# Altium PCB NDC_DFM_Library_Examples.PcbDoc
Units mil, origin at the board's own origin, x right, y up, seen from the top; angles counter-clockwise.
Board outline 8415 x 4965 mil, 4 copper layers (Top Layer, Mid-Layer 1, Mid-Layer 2, Bottom Layer); 33 components, 0 nets, 219 pads, 31 vias.
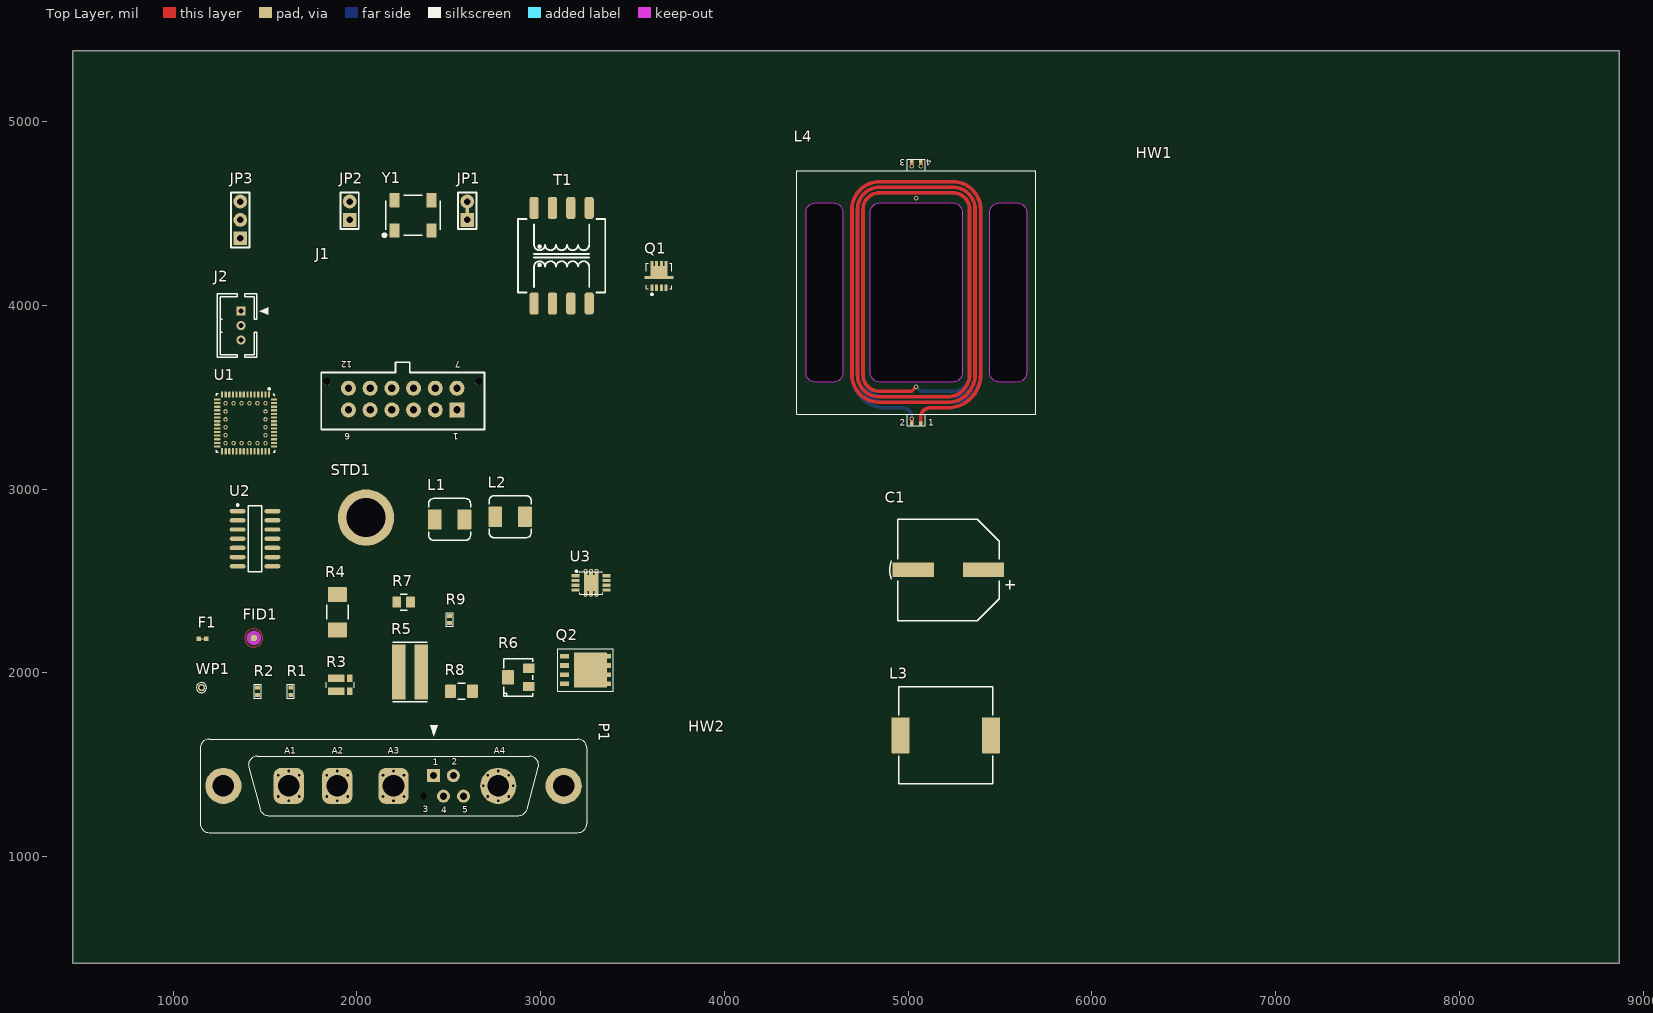
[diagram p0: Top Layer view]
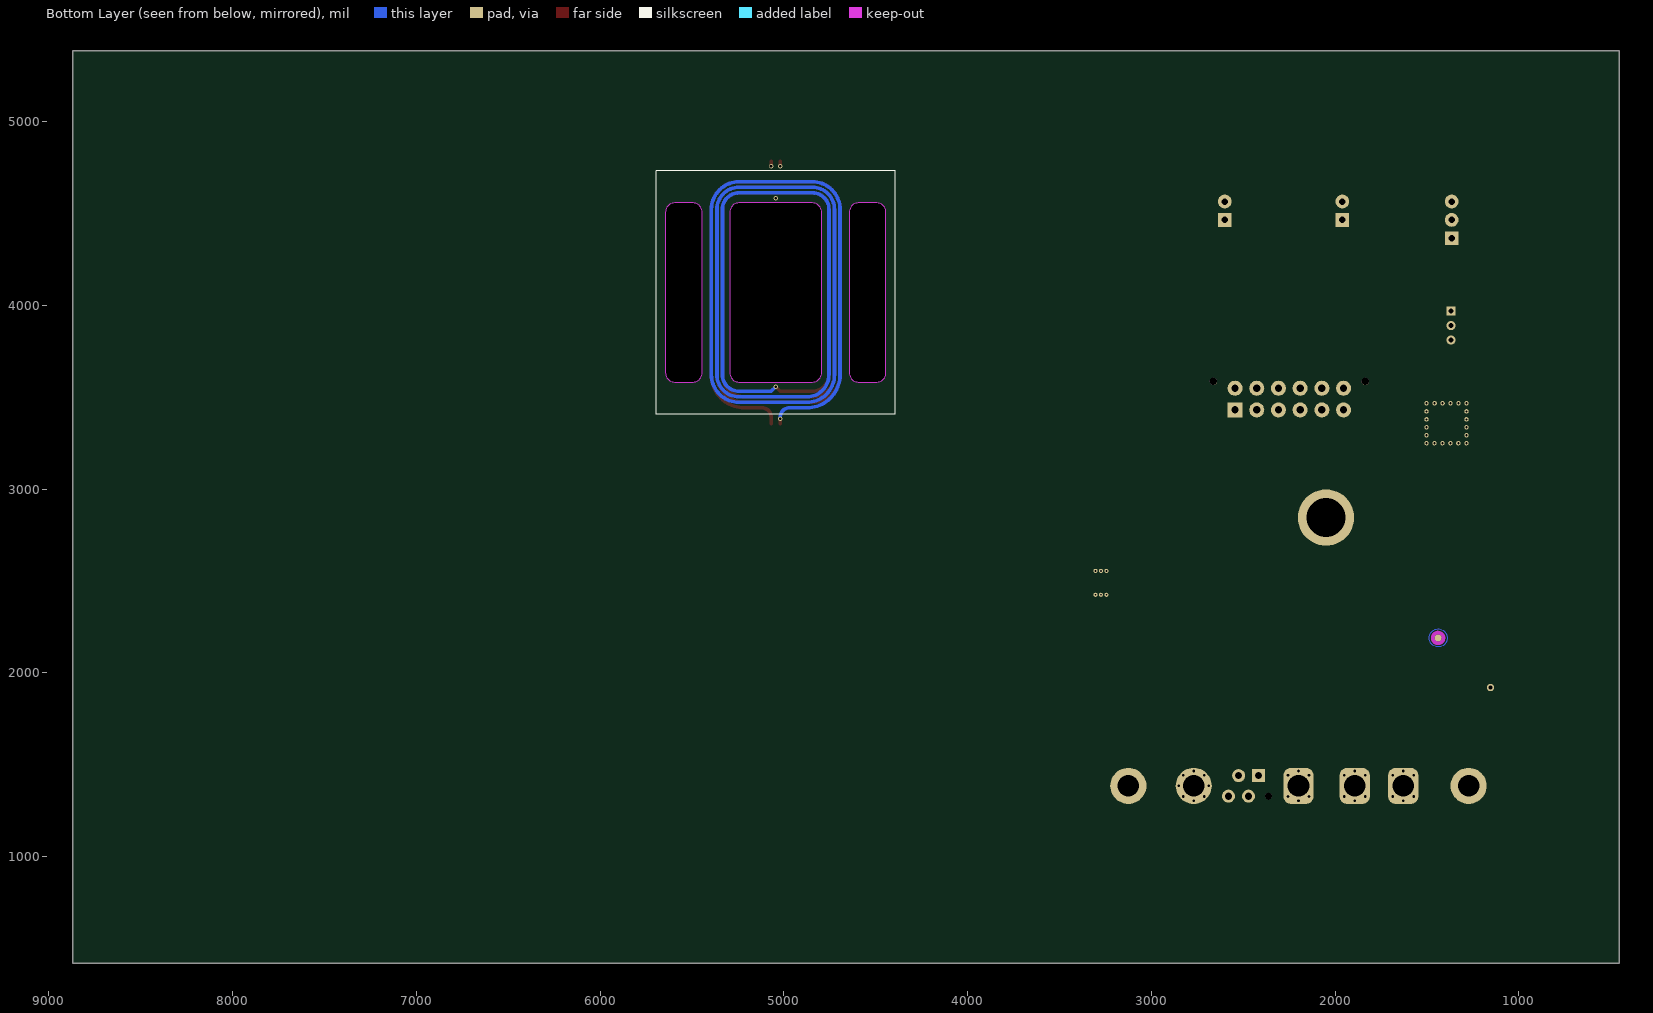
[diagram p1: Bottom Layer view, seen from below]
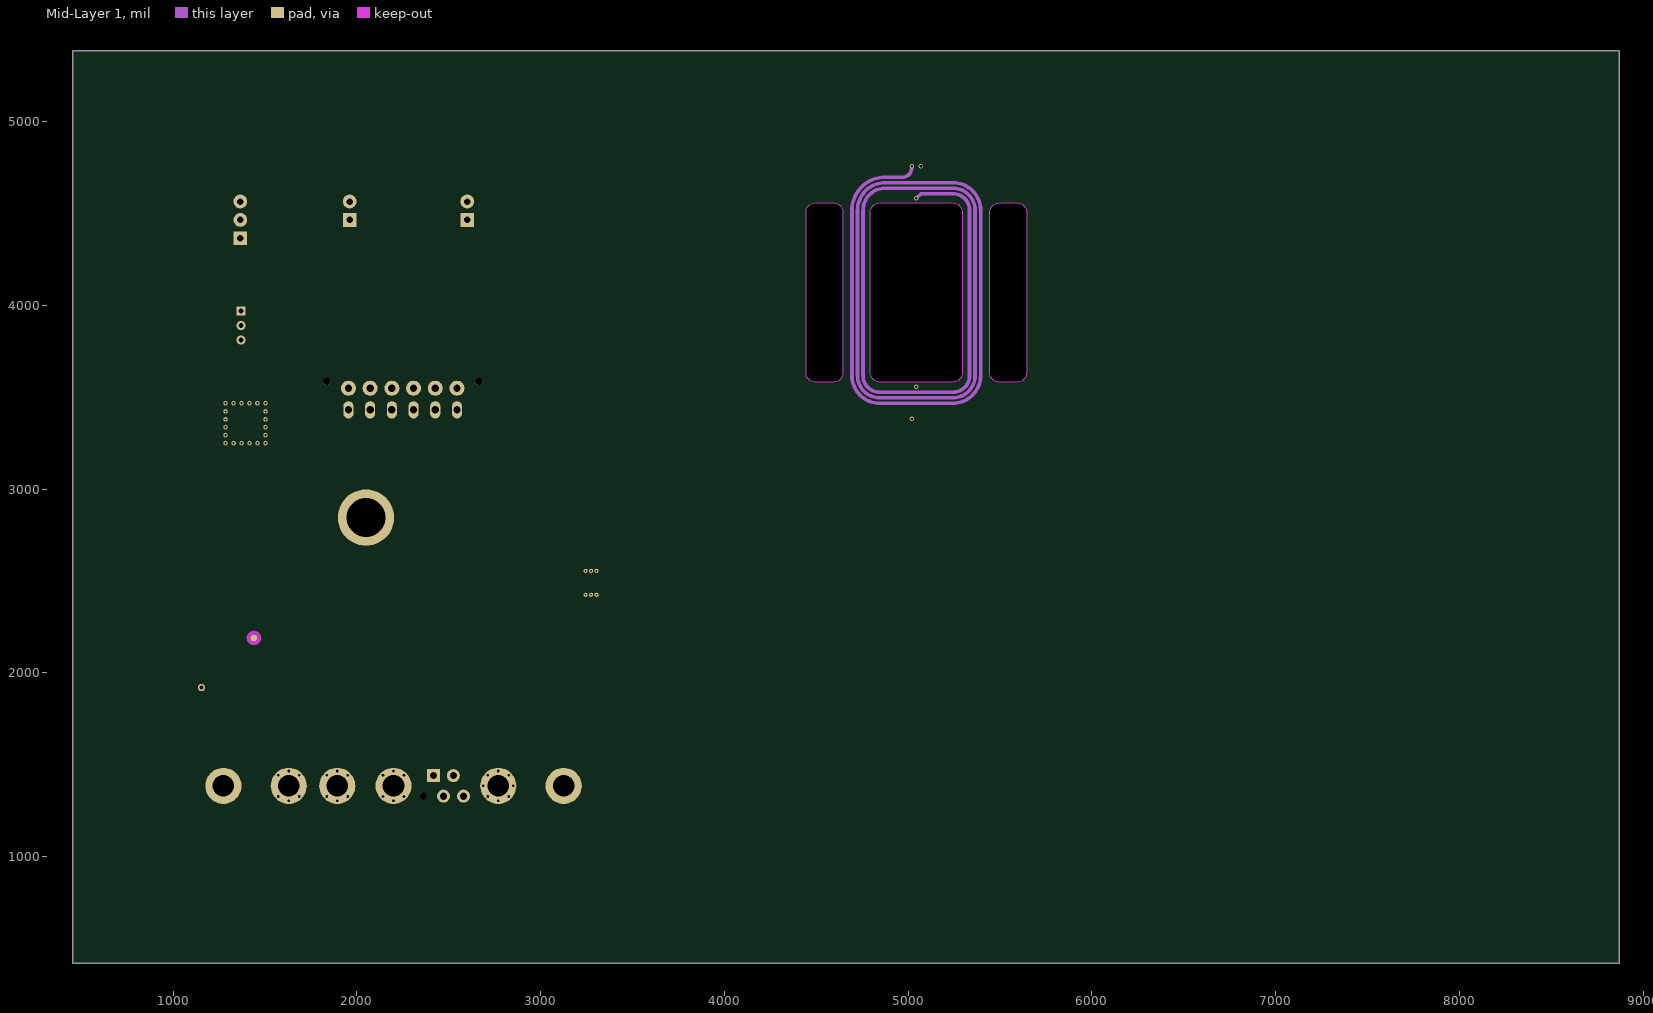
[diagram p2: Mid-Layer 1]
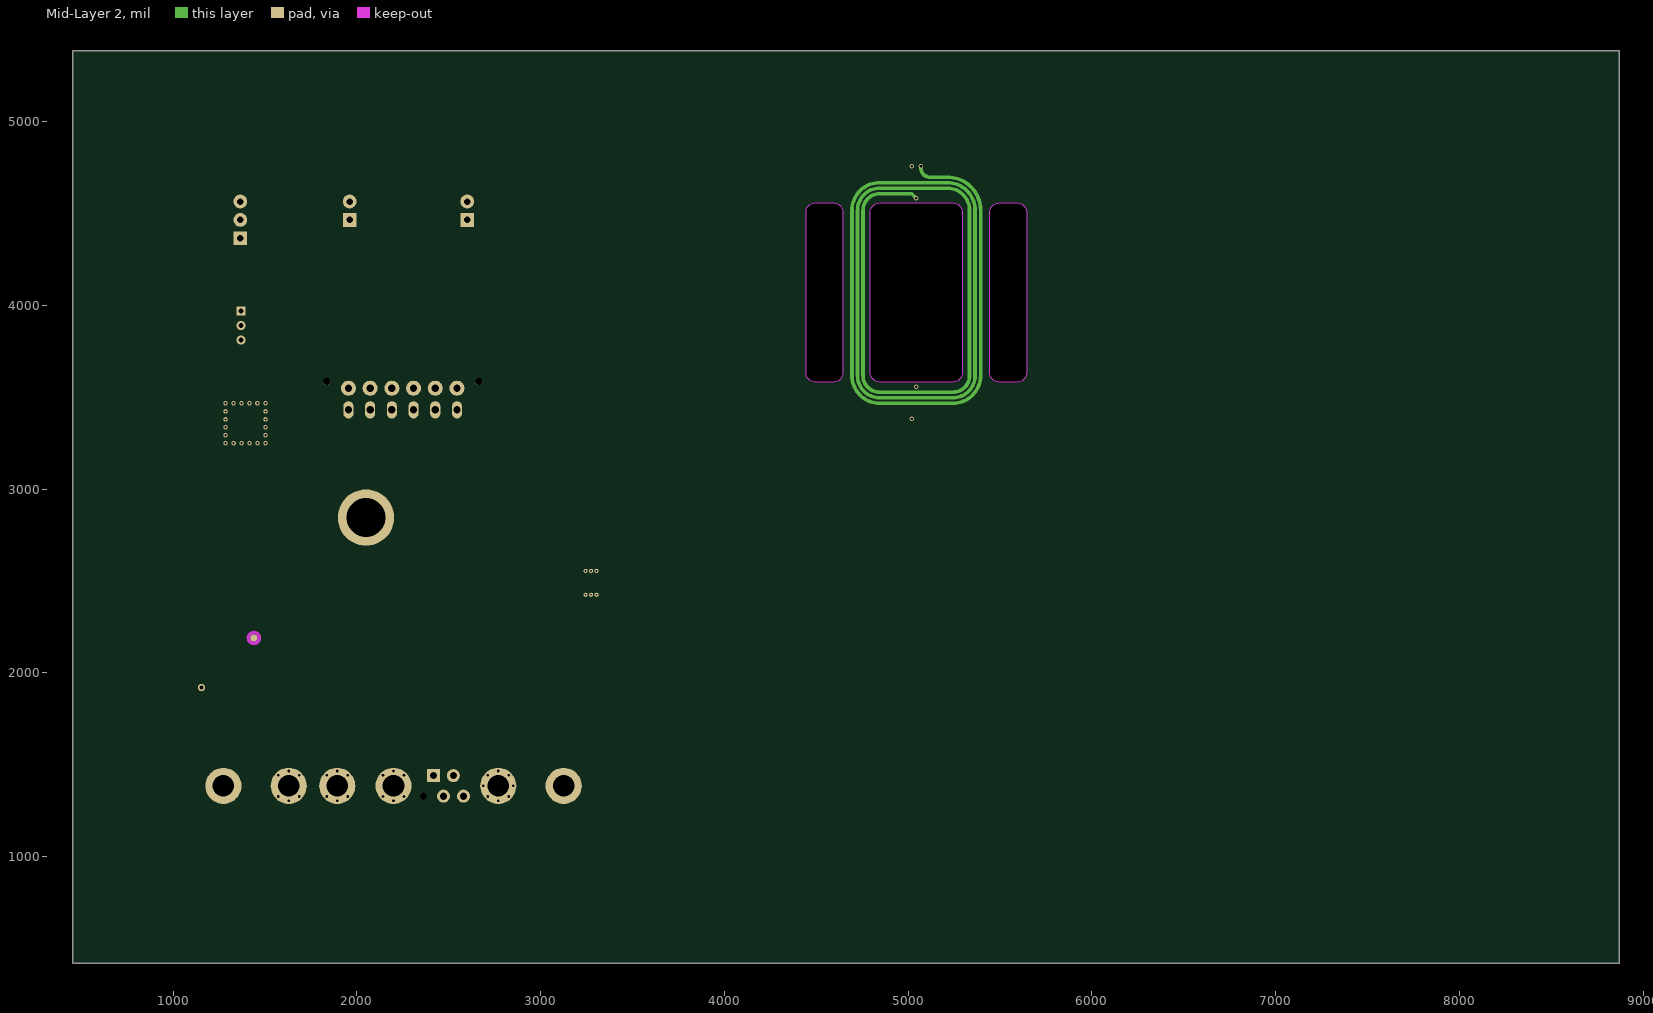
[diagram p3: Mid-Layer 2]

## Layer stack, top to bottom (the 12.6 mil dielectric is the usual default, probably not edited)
Top Solder: solder mask 0.4, Solder Resist, Dk 3.5
Top Layer: signal copper 1.4
Dielectric 1: dielectric 12.6, FR-4, Dk 4.8
Mid-Layer 1: signal copper 1.4
Dielectric2: dielectric 12.6, FR-4, Dk 4.8
Mid-Layer 2: signal copper 1.4
Dielectric3: dielectric 12.6, FR-4, Dk 4.8
Bottom Layer: signal copper 1.4
Bottom Solder: solder mask 0.4, Solder Resist, Dk 3.5

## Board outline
455,420 455,5385 8870,5385 8870,420

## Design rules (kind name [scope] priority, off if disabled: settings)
Clearance [All] p1: gap=10
Height [All] p1: minheight=0 maxheight=4000 prefheight=500
HoleSize [All] p1: absolutevalues=TRUE maxlimit=1000 minlimit=1 maxpercent=80.000 minpercent=20.000
PolygonConnect [All] p1: connectstyle=Relief reliefconductorwidth=10 reliefentries=4 polygonreliefangle="90 Angle" airgapwidth=10
RoutingVias [All] p1: holewidth=28 width=50 viastyle="Through Hole" minholewidth=7 minwidth=10 maxholewidth=1000 maxwidth=1000
SolderMaskExpansion [All] p1: expansion=4
Width [All] p1: maxlimit=30 minlimit=10 preferedwidth=10
28 further rules are at their usual default settings.

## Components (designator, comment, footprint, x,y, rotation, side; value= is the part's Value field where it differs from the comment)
C1 "CAP,ALUM,227,63V,20%,SMD" PANASONIC_CAP_SM_H13 5220,2560 r0 top
F1 "20A" PCB_FUSE-20A 1160,2185 r0 top net-tie
FID1 "FID" PCB_FID-TARGET-SM 1440,2190 r90 top
HW1 "HANDLE 3.00\"" KEYSTONE_HANDLE-7173 7230,4570 r0 top
HW2 "BRACKET,RA,6-32,THRD,0.165\"D,KEYSTONE,617" KEYSTONE_BRACKET-617 4100,1395 r0 top
J1 "HEADER,12P,MICROFIT,3MM DUAL V" MOLEX_43045-1212 2250,3490 r0 top
J2 "HEADER,3P,PH TOP,2MM" JST_B3B-PH-K-S 1370,3890 r90 top
JP1 "Breakaway Header, 0.1\"" TE_HDR1X2-CUT-TRACE 2601.24,4515.08 r90 top
JP2 "Breakaway Header, 0.1\"" TE_HDR1X2 1961.24,4465.08 r90 top
JP3 "Breakaway Header, 0.1\"" TE_HDR1X3 1366.24,4365.08 r90 top
L1 "IND,2.2uH,2020,5.5A,20%" VISHAY_IND-IHLP2020CZ-11 2505,2835 r0 top
L2 "IND,4.7uH,202,5.2A,20%" VISHAY_IND-IHLP2020CZ-11 2835,2850 r0 top
L3 "IND,250nH,SM,50A,81A ISAT" VISHAY-IND-WE-HCM 5205,1660 r0 top
L4 "IND,Etched" GENERIC_PLANAR-1:1 5045,4070 r90 top net-tie
P1 "JACK-M,9P,DSUB,MXD SIG" FCT_DB-9W4-M-S-PCB-MOD 2200,1385 r0 top
Q1 "TRAN,P-CH,PP1212-8,-60V,-8A" VISHAY_QFN65P330X330X112-10N 3645,4160 r90 top
Q2 "TRAN,N-CH,TDFN,60V,100A" INFINEON_TDSON-8 3245,2015 r0 top
R1 "RES,243K,0402,1%,1/16W" STACKPOLE_RESC1005X04N(0402) 1640,1900 r90 top
R2 "RES,1.4K,0402,1%,1/10W" STACKPOLE_RESC1005X04N(0402) 1460,1900 r90 top
R3 "RES-SENSOR,R004,0612,1%,1W" VISHAY_RES1632(0612)-RSNS 1910,1935 r0 top
R4 "RES,750K,MELF0204,1%,1W" VISHAY_MELF-MMB-0207 1895,2330 r90 top
R5 "RES,4.7K,1225WIDE,1%,2W" VISHAY_RES3263(1225) 2290,2005 r90 top
R6 "RES-POT,10K,SM,10%,1/4W" RPOT_3224W_44W 2880,1975 r0 top
R7 "RES,35.7K,MELF010,0.1%,1/5W" VISHAY_MELF-MMU-0102 2255,2385 r0 top
R8 "RES,100K,MELF0204,0.1%,1/4W" VISHAY_MELF-MMA-0204 2570,1900 r0 top
R9 "RES,0R00,0402,1/10W" STACKPOLE_RESC1005X04N(0402) 2505,2290 r90 top
STD1 "STANDOFF,PEM,3.6X4,CS,SMT" PENN_PEM-SMTSO-3.6-4DT 2050,2845 r0 top
T1 "XFRMR,1:1,SMD" PPT_PT4812 3115,4270 r0 top
U1 "IC_CYPRESS_USB-INTERFACE_CY7C68001-56LFC" CYPRESS_QFN50P800X800-HS-57 1395,3360 r0 top
U2 "IC_QUAD-AND-GATE_SN74HCT08DR_TI" TI_SOIC_14 1446.24,2730.08 r0 top
U3 "DISCRETE_OP-AMP_THS4631DGN_TI" TI_DGN8-EP 3275,2490 r0 top
WP1 "PAD,WIRE,28AWG,TH" GENERIC_WP28 1155,1920 r0 top
Y1 "ECS-3953M-1000-AU-TR" ECS_3953M-1000-AU-TR 2306.24,4490.08 r0 top

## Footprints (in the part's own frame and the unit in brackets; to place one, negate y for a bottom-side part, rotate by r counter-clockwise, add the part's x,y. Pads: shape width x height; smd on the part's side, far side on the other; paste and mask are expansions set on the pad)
CYPRESS_QFN50P800X800-HS-57 [mm] "Quad Flat No Lead; 56 Terminals; Body 8 x 8 mm; Pitch 0.5 mm, Punch Version"
  rrect50% 0.305x0.86 smd mask+0.051: 1(3.25,3.92) 14(-3.25,3.92) 29(-3.25,-3.92) 42(3.25,-3.92)
  rrect50% 0.305x0.86 smd mask+0.038: 2(2.75,3.92) 3(2.25,3.92) 4(1.75,3.92) 5(1.25,3.92) 6(0.75,3.92) 7(0.25,3.92) 8(-0.25,3.92) 9(-0.75,3.92) 10(-1.25,3.92) 11(-1.75,3.92) 12(-2.25,3.92) 13(-2.75,3.92) 30(-2.75,-3.92) 31(-2.25,-3.92) 32(-1.75,-3.92) 33(-1.25,-3.92) 34(-0.75,-3.92) 35(-0.25,-3.92) 36(0.25,-3.92) 37(0.75,-3.92) 38(1.25,-3.92) 39(1.75,-3.92) 40(2.25,-3.92) 41(2.75,-3.92)
  rrect50% 0.86x0.305 smd mask+0.051: 15(-3.92,3.25) 28(-3.92,-3.25) 43(3.92,-3.25) 56(3.92,3.25)
  rrect50% 0.86x0.305 smd mask+0.038: 16(-3.92,2.75) 17(-3.92,2.25) 18(-3.92,1.75) 19(-3.92,1.25) 20(-3.92,0.75) 21(-3.92,0.25) 22(-3.92,-0.25) 23(-3.92,-0.75) 24(-3.92,-1.25) 25(-3.92,-1.75) 26(-3.92,-2.25) 27(-3.92,-2.75) 44(3.92,-2.75) 45(3.92,-2.25) 46(3.92,-1.75) 47(3.92,-1.25) 48(3.92,-0.75) 49(3.92,-0.25) 50(3.92,0.25) 51(3.92,0.75) 52(3.92,1.25) 53(3.92,1.75) 54(3.92,2.25) 55(3.92,2.75)
  round 0.6 hole 0.3: 56(-2.775,-2.8) 56(-2.775,-1.7) 56(-2.775,-0.6) 56(-2.775,0.5) 56(-2.775,1.6) 56(-2.775,2.725) 56(-1.675,2.725) 56(-1.65,-2.8) 56(-0.575,2.725) 56(-0.55,-2.8) 56(0.525,2.725) 56(0.55,-2.8) 56(1.625,2.725) 56(1.65,-2.8) 56(2.75,-2.8) 56(2.75,-1.7) 56(2.75,-0.6) 56(2.75,0.5) 56(2.75,1.6) 56(2.75,2.725)
  silkscreen extent -4.05,-4.05 4.05,4.83, body extent -4.27,-4.32 4.31,4.2, height 0.55
ECS_3953M-1000-AU-TR [mm] "SMD CLOCK OSCILLATOR"
  rrect10% 1.4x2 smd: 1(-2.54,-2.1) 2(2.54,-2.1) 3(2.54,2.1) 4(-2.54,2.1)
  silkscreen extent -4.15,-2.95 3.75,2.75, body extent -3.5,-2.5 3.5,2.5, height 1.71
FCT_DB-9W4-M-S-PCB-MOD [mm] "FCT FM9W4P1-2464, Conn, DB, Mixed, 9 Pins, 4 Wide, Male, Straight, PCB Mt"
  rect 1.803x1.803 hole 1: 1(5.54,1.42)
  round 1.803 hole 1: 2(8.28,1.42) 4(6.91,-1.42) 5(9.68,-1.42)
  round 0.889 hole 1 unplated: 3(4.14,-1.42)
  rrect50% 4.2x5 / inner round 5 / far side rrect50% 4.2x5 hole 3: A1(-14.48,0) A2(-7.77,0) A3(0,0)
  round 5 hole 3: A4(14.48,0) C(-23.52,0) C(23.52,0)
  silkscreen extent -26.7,-6.45 26.7,8.38, body extent -26.47,-6.27 26.53,6.23, height 13.8
GENERIC_PLANAR-1:1 [mil]
  rrect10% 20x20 smd paste-50 mask-50: 1(-712.5,-25) 2(-712.5,25) 3(712.5,25) 4(712.5,-25)
  Top Layer lines w20: -712.5,25 -687.5,25 ; 687.5,25 712.5,25 ; -512.5,0 -537.5,25 -537.5,200 cw(c-447.5,200) -447.5,290 452.5,290 cw(c452.5,200) 542.5,200 542.5,-200 cw(c452.5,-200) 452.5,-290 -447.5,-290 cw(c-447.5,-170) -567.5,-170 -567.5,0 -567.5,200 cw(c-447.5,200) -447.5,320 452.5,320 cw(c452.5,200) 572.5,200 572.5,-200 cw(c452.5,-200) 452.5,-320 -447.5,-320 cw(c-447.5,-170) -597.5,-170 -597.5,0 -597.5,200 cw(c-447.5,200) -447.5,350 452.5,350 cw(c452.5,200) 602.5,200 602.5,-200 cw(c452.5,-200) 452.5,-350 -447.5,-350 cw(c-447.5,-170) -627.5,-170 -627.5,-75 ccw(c-677.5,-75) -677.5,-25 -712.5,-25 ; 687.5,-25 712.5,-25
  Mid-Layer 1 lines w20: 687.5,25 677.5,25 cw(c677.5,75) 627.5,75 627.5,170 ccw(c447.5,170) 447.5,350 -452.5,350 ccw(c-452.5,200) -602.5,200 -602.5,-200 ccw(c-452.5,-200) -452.5,-350 447.5,-350 ccw(c447.5,-200) 597.5,-200 597.5,0 597.5,170 ccw(c447.5,170) 447.5,320 -452.5,320 ccw(c-452.5,200) -572.5,200 -572.5,-200 ccw(c-452.5,-200) -452.5,-320 447.5,-320 ccw(c447.5,-200) 567.5,-200 567.5,0 567.5,170 ccw(c447.5,170) 447.5,290 -452.5,290 ccw(c-452.5,200) -542.5,200 -542.5,-200 ccw(c-452.5,-200) -452.5,-290 447.5,-290 ccw(c447.5,-200) 537.5,-200 537.5,-25 512.5,0
  Mid-Layer 2 lines w20: 512.5,0 537.5,25 537.5,200 ccw(c447.5,200) 447.5,290 -452.5,290 ccw(c-452.5,200) -542.5,200 -542.5,-200 ccw(c-452.5,-200) -452.5,-290 447.5,-290 ccw(c447.5,-170) 567.5,-170 567.5,0 567.5,200 ccw(c447.5,200) 447.5,320 -452.5,320 ccw(c-452.5,200) -572.5,200 -572.5,-200 ccw(c-452.5,-200) -452.5,-320 447.5,-320 ccw(c447.5,-170) 597.5,-170 597.5,0 597.5,200 ccw(c447.5,200) 447.5,350 -452.5,350 ccw(c-452.5,200) -602.5,200 -602.5,-200 ccw(c-452.5,-200) -452.5,-350 447.5,-350 ccw(c447.5,-170) 627.5,-170 627.5,-75 cw(c677.5,-75) 677.5,-25 687.5,-25
  Bottom Layer lines w20: -687.5,25 -677.5,25 ccw(c-677.5,75) -627.5,75 -627.5,170 cw(c-447.5,170) -447.5,350 452.5,350 cw(c452.5,200) 602.5,200 602.5,-200 cw(c452.5,-200) 452.5,-350 -447.5,-350 cw(c-447.5,-200) -597.5,-200 -597.5,0 -597.5,170 cw(c-447.5,170) -447.5,320 452.5,320 cw(c452.5,200) 572.5,200 572.5,-200 cw(c452.5,-200) 452.5,-320 -447.5,-320 cw(c-447.5,-200) -567.5,-200 -567.5,0 -567.5,170 cw(c-447.5,170) -447.5,290 452.5,290 cw(c452.5,200) 542.5,200 542.5,-200 cw(c452.5,-200) 452.5,-290 -447.5,-290 cw(c-447.5,-200) -537.5,-200 -537.5,-25 -512.5,0
  Keep-Out Layer board cut-out: -487.5,-550 -487.5,-450 -483.69,-430.87 -472.85,-414.64 -456.63,-403.81 -437.5,-400 -437.5,-400 437.5,-400 456.63,-403.81 472.86,-414.64 483.69,-430.87 487.5,-450 487.5,-450 487.5,-550 483.69,-569.13 472.86,-585.35 456.63,-596.19 437.5,-600 437.5,-600 -437.5,-600 -456.63,-596.19 -472.85,-585.35 -483.69,-569.13 -487.5,-550
  Keep-Out Layer board cut-out: -487.5,450 -487.5,550 -483.69,569.13 -472.85,585.36 -456.63,596.19 -437.5,600 -437.5,600 437.5,600 456.63,596.19 472.86,585.36 483.69,569.13 487.5,550 487.5,550 487.5,450 483.69,430.87 472.86,414.65 456.63,403.81 437.5,400 437.5,400 -437.5,400 -456.63,403.81 -472.85,414.65 -483.69,430.87 -487.5,450
  Keep-Out Layer board cut-out: -487.5,-200 -487.5,200 -483.69,219.13 -472.85,235.36 -456.63,246.19 -437.5,250 -437.5,250 437.5,250 456.63,246.19 472.86,235.36 483.69,219.13 487.5,200 487.5,200 487.5,-200 483.69,-219.13 472.86,-235.35 456.63,-246.19 437.5,-250 437.5,-250 -437.5,-250 -456.63,-246.19 -472.85,-235.35 -483.69,-219.13 -487.5,-200
  silkscreen extent -725,-650 725,650, body extent -462,-575 463,575, height 70
GENERIC_WP28 [mil] "PAD,WIRE,28AWG,TH"
  round 40 hole 22: WP28(0,0)
  silkscreen extent -27,-27 28,27, body extent -12,-12 12,12, height 258
INFINEON_TDSON-8 [mm] "INFINEON  SuperS08 125W"
  rect 4.6x4.8 smd: D(0.7,0)
  rect 1.2x0.65 smd: D(2.9,-1.905) D(2.9,-0.635) D(2.9,0.635) D(2.9,1.905) G(-2.9,-1.905) S(-2.9,-0.635) S(-2.9,0.635) S(-2.9,1.905)
  silkscreen extent -3.81,-2.92 3.81,2.92, body extent -3.12,-2.63 3.12,2.63, height 1.12
JST_B3B-PH-K-S [mm]
  rrect15% 1.25x1.25 hole 0.7: 1(2,0)
  round 1.25 hole 0.7: 2(0,0) 3(-2,0)
  silkscreen extent -4.4,-3.75 4.4,3.3, body extent -3.95,-1.7 3.95,2.8, height 6
KEYSTONE_BRACKET-617 [mil] "BRACKET,RIGHT-ANGL,THRD,6-32 (STEEL)"
  body extent -299,-250 201,250, height 578
KEYSTONE_HANDLE-7173 [mil] "HANDLE,ALUM,BLK,3.00\",8-32"
  body extent -125,-3125 125,125, height 1828
MOLEX_43045-1212 [mm] "Header, 12 Position, Pitch 3.0mm, Body 21.65 mm L X 7.37mm W, Height 9.91mm"
  rect 2.083x2.083 / inner oval 1.4x2.4 / far side rect 2.083x2.083 hole 1.02 mask+0.051: 1(7.5,-1.5)
  round 2.083 / inner oval 1.4x2.4 / far side round 2.083 hole 1.02 mask+0.051: 2(4.5,-1.5) 3(1.5,-1.5) 4(-1.5,-1.5) 5(-4.5,-1.5) 6(-7.5,-1.5)
  round 2.083 hole 1.02 mask+0.051: 7(7.5,1.5) 8(4.5,1.5) 9(1.5,1.5) 10(-1.5,1.5) 11(-4.5,1.5) 12(-7.5,1.5)
  round 1.016 hole 1.02 unplated: MNT(-10.5,2.44) MNT(10.5,2.44)
  silkscreen extent -11.25,-4.22 11.3,5.1, body extent -11.07,-4.39 11.08,6.46, height 25
PANASONIC_CAP_SM_H13 [mm]
  rect 5.7x2 smd: 1(4.85,0) 2(-4.85,0)
  silkscreen extent -8.11,-7 9.15,7, body extent -6.9,-6.75 6.9,6.75, height 13.5
PCB_FID-TARGET-SM [mm]
  round 1 on Mech6 paste-0.55 mask+1: FID1(0,0)
  round 1 all layers, no hole paste-0.762 mask+0.9: FIDM(0,0)
  Top Layer circle w0.155: c0,0 r1.25
  Bottom Layer circle w0.155: c0,0 r1.25
  Keep-Out Layer circle w0.5: c0,0 r0.75
PCB_FUSE-20A [mm]
  rect 0.6x0.6 smd: 1(-0.527,-0.001) 2(0.523,-0.001)
  rrect10% 1x0.125 smd paste-2 mask-2: 1(0,0)
PENN_PEM-SMTSO-3.6-4DT [mm] "PEM Standoff SMTSO-3.6-4DT, Matte Tin, Surface Mount Solder, ReelFast"
  round 7.77 hole 5.41: MH(0,0)
  body extent -3.57,-3.57 3.57,3.57, height 4
PPT_PT4812 [mm] "Transformer for Digital Audio Data Transmission"
  rrect50% 1.27x3.05 smd: 1(3.81,6.605) 2(1.27,6.605) 3(-1.27,6.605) 4(-3.81,6.605) 5(-3.81,-6.605) 6(-1.27,-6.605) 7(1.27,-6.605) 8(3.81,-6.605)
  silkscreen extent -6.03,-5.08 6.03,5.08, body extent -5.97,-6.64 6.09,6.89, height 8.86
RPOT_3224W_44W [mm] "Potentiometer, SMT 4mm, Multiturn Cermet, Sealed"
  rrect10% 1.6x1.3 smd: 1(1.45,1.25) 3(1.45,-1.25)
  rrect10% 1.6x2 smd: 2(-1.45,0)
  silkscreen extent -2,-2.6 2,2.6, body extent -1.96,-2.41 1.97,2.41, height 5.28
STACKPOLE_RESC1005X04N(0402) [mm] "Chip Resistor, Body 1.0x0.5mm, Height 0.40mm, IPC Medium Density"
  rect 0.55x0.65 smd: 1(-0.5,0) 2(0.5,0)
  silkscreen extent -0.95,-0.5 0.95,0.5, body extent -0.52,-0.27 0.53,0.28, height 0.45
TE_HDR1X2 [mm] "Connector; Header; 2 Position"
  rect 1.905x1.905 hole 0.9: 1(0,0)
  round 1.905 hole 0.9: 2(2.54,0)
  silkscreen extent -1.27,-1.27 3.81,1.27, body extent -1.27,-1.27 3.81,1.27, height 8.25
TE_HDR1X2-CUT-TRACE [mm] "Connector; Header; 2 Position"
  rect 1.905x1.905 hole 0.9: 1(-1.27,0)
  rrect10% 2.54x0.508 smd paste-2.667 mask-2.667: 1(0,0)
  round 1.905 hole 0.9: 2(1.27,0)
  silkscreen extent -2.54,-1.27 2.54,1.27, body extent -2.54,-1.27 2.54,1.27, height 8.25
TE_HDR1X3 [mm] "Connector; Header; 3 Position"
  rect 1.905x1.905 hole 0.9: 1(0,0)
  round 1.905 hole 0.9: 2(2.54,0) 3(5.08,0)
  silkscreen extent -1.27,-1.27 6.35,1.27, body extent -1.27,-1.27 6.35,1.27, height 8.25
TI_DGN8-EP [mil] "TSOP, 8-Leads, Body 3.1x3.1mm (max), Pitch 0.65mm, IPC Medium Density"
  rect 45x17.72 smd mask+0: 1(-84,38.39) 2(-84,12.8) 3(-84,-12.8) 4(-84,-38.39) 5(84,-38.39) 6(84,-12.8) 7(84,12.8) 8(84,38.39)
  round 22 hole 10: 9(-29.53,-65) 9(-29.53,65) 9(0,-65) 9(0,65) 9(29.53,-65) 9(29.53,65)
  rect 20x30 smd: 9(-29.53,-48.23) 9(-29.53,47.24) 9(0,-49.21) 9(0,47.24) 9(29.53,-49.21) 9(29.53,46.26)
  rect 78.74x86.61 smd: 9(0,0)
  silkscreen extent -84,-61 61,68, body extent -96,-59 97,59, height 38
TI_SOIC_14 [mm] "SOIC, 14-Leads, Body 8.65x3.95mm, Pitch 1.27mm, IPC Medium Density"
  oval 2.2x0.6 smd: 1(-2.4,3.81) 2(-2.4,2.54) 3(-2.4,1.27) 4(-2.4,0) 5(-2.4,-1.27) 6(-2.4,-2.54) 7(-2.4,-3.81) 8(2.4,-3.81) 9(2.4,-2.54) 10(2.4,-1.27) 11(2.4,0) 12(2.4,1.27) 13(2.4,2.54) 14(2.4,3.81)
  silkscreen extent -2.52,-4.55 0.9,4.78, body extent -2.9,-4.26 2.9,4.26, height 1.75
VISHAY-IND-WE-HCM [mm] "WE-HCM SMD High-Current Flat Wire Inductor"
  rrect10% 2.5x5 smd: 1(-6.25,0) 2(6.25,0)
  silkscreen extent -6.5,-6.7 6.5,6.7, body extent -7,-6.5 7,6.5, height 9
VISHAY_IND-IHLP2020CZ-11 [mm] "Low Profile, High Current IHLP® Inductor"
  rrect10% 1.9x2.8 smd: 1(-2.05,0) 2(2.05,0)
  silkscreen extent -2.9,-2.9 2.9,2.9, body extent -2.75,-2.6 2.75,2.6, height 3
VISHAY_MELF-MMA-0204 [mm]
  rrect10% 1.5x1.8 smd: 1(-1.5,0) 2(1.5,0)
  silkscreen extent -0.5,-1.1 0.5,1.1, body extent -1.7,-0.7 1.7,0.7, height 1.4
VISHAY_MELF-MMB-0207 [mm]
  rrect10% 2.1x2.6 smd: 1(-2.45,0) 2(2.45,0)
  silkscreen extent -1,-1.5 1,1.5, body extent -2.65,-1.1 2.65,1.1, height 2.2
VISHAY_MELF-MMU-0102 [mm]
  rrect10% 1.2x1.5 smd: 1(-0.95,0) 2(0.95,0)
  silkscreen extent -0.5,-1.1 0.5,1.1, body extent -1,-0.55 1,0.55, height 1.1
VISHAY_QFN65P330X330X112-10N [mm] "QFN, 10-Leads, Body 3.4x3.4mm (max), Pitch 0.65mm, IPC Medium Density"
  rect 0.9x0.4 smd: 1(-1.625,0.975) 2(-1.625,0.325) 3(-1.625,-0.325) 4(-1.625,-0.975) 6(1.625,-0.975) 7(1.625,-0.325) 8(1.625,0.325) 9(1.625,0.975)
  rect 0.4x0.95 smd: 5(-0.203,1.524) 5(-0.203,-1.524)
  rect 1.8x2.4 smd: 5(0.5,0)
  silkscreen extent -2.67,-1.75 1.75,1.75, body extent -1.63,-1.7 1.64,1.7, height 1.13
VISHAY_RES1632(0612)-RSNS [mil] "4-Terminal, 1W, Current-sense Resistor"
  rrect10% 90x40 smd: 1(-22.5,35) 2(-22.5,-35)
  rrect10% 30x40 smd: 1(52.5,35) 2(52.5,-35)
  silkscreen extent -75,-15 75,15, body extent -60,-30 60,30, height 15
VISHAY_RES3263(1225) [mm] "Long Side Termination Thick Film Chip Resistor, 2W"
  rrect10% 7.6x1.9 smd: 1(0,1.55) 2(0,-1.55)
  silkscreen extent -4.1,-2.4 4.1,2.4, body extent -3.15,-1.55 3.15,1.55, height 0.63

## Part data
C1: library part DISCRETE_CAP_SM_227uF_63V_H13.5_PANASONIC
F1: library part PCB_FUSE-20A, "PCB FEATURE"
FID1: library part PCB_FID-TARGET-SM, "PCB FEATURE"
HW1: library part MECH_HANDLE_RACK_3IN_KEYSTONE, "HANDLE,ALUM,BLK,3.00\",8-32"
HW2: library part MECH_BRACKET_RA_KEYSTONE
J1: library part CONN_43045-1212_MOLEX
J2: library part CONN_B3B-PH-K-S_JST
JP1: library part CONN_JUMPER-2PIN-CUT-TRACE_TE, "Breakaway Header, 2.54mm (0.1\") Pitch"
JP2: library part CONN_JUMPER-2PIN_TE, "Breakaway Header, 2.54mm (0.1\") Pitch"
JP3: library part CONN_JUMPER-3PIN_TE, "Breakaway Header, 2.54mm (0.1\") Pitch"
L1: library part DISCRETE_IND-SM_2.2uH_5.5A_20%_VISHAY
L2: library part DISCRETE_IND-SM_4.7uH_5.2A_20%_VISHAY
L3: library part DISCRETE_IND-SM_250NH_50A_VISHAY
L4: library part PCB_IND-SM
P1: library part CONN_DB-9W4-M-S-PCB_FCT
Q1: library part DISCRETE_TRAN-SM_P-CH_SI7309DN_PP1212-8_VISHAY
Q2: library part DISCRETE_TRAN-SM_N-CH_60V_100A_TDSON-8_INFINEON
R1: library part DISCRETE_RES0402_243K_1%_1/16W_STACKPOLE
R2: library part DISCRETE_RES0402_1.4K_1%_1/10W_PANASONIC
R3: library part DISCRETE_RES0612_R004_1%_1W_VISHAY, "RES,R004,0612,1%,1W"
R4: library part DISCRETE_RES_MELF_0207_750K_1%_1W_VISHAY
R5: library part DISCRETE_RES1225_4.7K_1%_2W_1225WIDE_VISHAY
R6: library part DISCRETE_RES-SM-POT_10K_MULTI_1/4W_BiTECH
R7: library part DISCRETE_RES_MELF_010_35.7K_0.1%_1/5W_VISHAY
R8: library part DISCRETE_RES_MELF_0204_100K_0.1%_1/4W_VISHAY
R9: library part DISCRETE_RES0402_0R00_PANASONIC
STD1: library part MECH_STANDOFF_PEM_3.6X4_CS_SMT_PENN
T1: library part DISCRETE_XFRMR_PT4812_PPT
U1: "CY7C68001-56LFC, EZ-USB SX2 High-Speed USB Interface"
U2: "LogicGate_AND"
U3: "Operational Amplifier"
WP1: library part PCB_WIRE_PAD_28AWG
Y1: library part IC_ECS_OSC-100.000-MHZ-3.3V-SMD, "OSC 100.000 MHZ 3.3V SMD"

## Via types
v1: diameter 32, hole 15, Top Layer to Bottom Layer, 26 vias
v2: diameter 25, hole 15, Top Layer to Bottom Layer, tented both sides, 5 vias

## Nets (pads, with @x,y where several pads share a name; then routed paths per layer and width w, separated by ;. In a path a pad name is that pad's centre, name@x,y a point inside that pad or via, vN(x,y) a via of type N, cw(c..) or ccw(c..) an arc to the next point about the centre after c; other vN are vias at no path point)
pads on no net: C1.1 C1.2 F1.1 F1.2 FID1.FID1 FID1.FIDM J1.1 J1.2 J1.3 J1.4 J1.5 J1.6 J1.7 J1.8 J1.9 J1.10 J1.11 J1.12 J1.MNT J2.1 J2.2 J2.3 JP1.1 JP1.2 JP2.1 JP2.2 JP3.1 JP3.2 JP3.3 L1.1 L1.2 L2.1 L2.2 L3.1 L3.2 L4.1 L4.2 L4.3 L4.4 P1.1 P1.2 P1.3 P1.4 P1.5 P1.A1 P1.A2 P1.A3 P1.A4 P1.C Q1.1 Q1.2 Q1.3 Q1.4 Q1.5 Q1.6 Q1.7 Q1.8 Q1.9 Q2.D Q2.G Q2.S R1.1 R1.2 R2.1 R2.2 R3.1 R3.2 R4.1 R4.2 R5.1 R5.2 R6.1 R6.2 R6.3 R7.1 R7.2 R8.1 R8.2 R9.1 R9.2 STD1.MH T1.1 T1.2 T1.3 T1.4 T1.5 T1.6 T1.7 T1.8 U1.1 U1.2 U1.3 U1.4 U1.5 U1.6 U1.7 U1.8 U1.9 U1.10 U1.11 U1.12 U1.13 U1.14 U1.15 U1.16 U1.17 U1.18 U1.19 U1.20 U1.21 U1.22 U1.23 U1.24 U1.25 U1.26 U1.27 U1.28 U1.29 U1.30 U1.31 U1.32 U1.33 U1.34 U1.35 U1.36 U1.37 U1.38 U1.39 U1.40 U1.41 U1.42 U1.43 U1.44 U1.45 U1.46 U1.47 U1.48 U1.49 U1.50 U1.51 U1.52 U1.53 U1.54 U1.55 U1.56 U2.1 U2.2 U2.3 U2.4 U2.5 U2.6 U2.7 U2.8 U2.9 U2.10 U2.11 U2.12 U2.13 U2.14 U3.1 U3.2 U3.3 U3.4 U3.5 U3.6 U3.7 U3.8 U3.9 WP1.WP28 Y1.1 Y1.2 Y1.3 Y1.4
copper on no net:
  other v1: 1629.92,1303.76 1894.09,1303.76 2200,1303.76 2770.08,1303.76 1572.48,1327.56 1687.36,1327.56 1836.65,1327.56 1951.54,1327.56 2142.56,1327.56 2257.44,1327.56 2712.64,1327.56 2827.52,1327.56 2688.84,1385 2851.32,1385 1572.48,1442.44 1687.36,1442.44 1836.65,1442.44 1951.54,1442.44 2142.56,1442.44 2257.44,1442.44 2712.64,1442.44 2827.52,1442.44 1629.92,1466.24 1894.09,1466.24 2200,1466.24 2770.08,1466.24
  other v2: 5020,3382.5 5045,3557.5 5045,4582.5 5020,4757.5 5070,4757.5

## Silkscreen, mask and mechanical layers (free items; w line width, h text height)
M01 - BOARD OUTLINE:
  the board outline again, w3.94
